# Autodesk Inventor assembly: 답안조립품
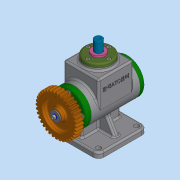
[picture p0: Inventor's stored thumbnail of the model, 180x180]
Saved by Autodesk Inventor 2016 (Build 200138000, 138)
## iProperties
Created: 2019-01
Part Number: 답안조립품
Material: 일반
Document SubType Name: Assembly
Designer: 3sil_cad018
Author: 3sil_cad018
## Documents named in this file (18)
- C:\Users\3sil_cad018\Desktop\390108V1001\답안조립품.iam
- C:\Users\3sil_cad018\Desktop\390108V1001\본체.ipt
- C:\Users\3sil_cad018\Desktop\390108V1001\가변스프링.ipt
- C:\Users\3sil_cad018\Desktop\390108V1001\뒤커버.ipt
- C:\Users\3sil_cad018\Desktop\390108V1001\멈춤링.ipt
- C:\Users\3sil_cad018\Desktop\390108V1001\베어링 6203.ipt
- C:\Users\3sil_cad018\Desktop\390108V1001\볼트 M4.ipt
- C:\Users\3sil_cad018\Desktop\390108V1001\부시.ipt
- C:\Users\3sil_cad018\Desktop\390108V1001\상부커버.ipt
- C:\Users\3sil_cad018\Desktop\390108V1001\스퍼기어.ipt
- C:\Users\3sil_cad018\Desktop\390108V1001\스프링와셔.ipt
- C:\Users\3sil_cad018\Desktop\390108V1001\스프링조립용 와셔.ipt
- C:\Users\3sil_cad018\Desktop\390108V1001\슬라이더.ipt
- C:\Users\3sil_cad018\Desktop\390108V1001\앞커버.ipt
- C:\Users\3sil_cad018\Desktop\390108V1001\오일 실 17 30 5.ipt
- C:\Users\3sil_cad018\Desktop\390108V1001\키 4x4x12.ipt
- C:\Users\3sil_cad018\Desktop\390108V1001\편심축.ipt
- C:\Users\3sil_cad018\Desktop\390108V1001\평와셔.ipt
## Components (1 placed, 1 different names)
1. 가변스프링:1
